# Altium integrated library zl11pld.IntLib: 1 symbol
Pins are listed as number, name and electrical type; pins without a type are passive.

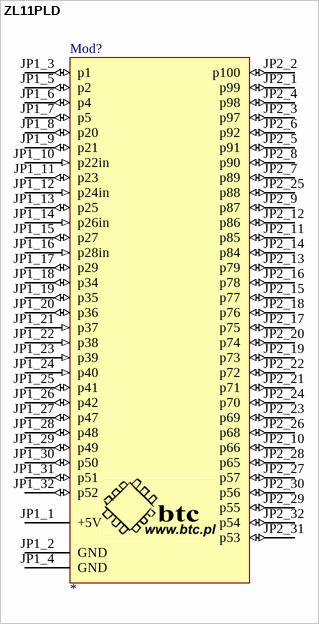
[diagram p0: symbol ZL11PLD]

## ZL11PLD
designator Mod?
Cyclone FPGA DIPmodule by www.kamami.com
footprint ZL11PLD_PCB
pins: JP1_1 +5V (power), JP1_2 GND (power), JP1_3 p1 (io), JP1_4 GND (power), JP1_5 p2 (io), JP1_6 p4 (io), JP1_7 p5 (io), JP1_8 p20 (io), JP1_9 p21 (io), JP1_10 p22in (in), JP1_11 p23 (io), JP1_12 p24in (in), JP1_13 p25 (io), JP1_14 p26in (in), JP1_15 p27 (io), JP1_16 p28in (in), JP1_17 p29 (io), JP1_18 p34 (io), JP1_19 p35 (io), JP1_20 p36 (io), JP1_21 p37 (in), JP1_22 p38 (in), JP1_23 p39 (in), JP1_24 p40 (in), JP1_25 p41 (io), JP1_26 p42 (io), JP1_27 p47 (io), JP1_28 p48 (io), JP1_29 p49 (io), JP1_30 p50 (io), JP1_31 p51 (io), JP1_32 p52 (io), JP2_1 p99 (io), JP2_2 p100 (io), JP2_3 p97 (io), JP2_4 p98 (io), JP2_5 p91 (io), JP2_6 p92 (io), JP2_7 p89 (io), JP2_8 p90 (io), JP2_9 p87 (io), JP2_10 p66 (io), JP2_11 p85 (io), JP2_12 p86 (io), JP2_13 p79 (io), JP2_14 p84 (io), JP2_15 p77 (io), JP2_16 p78 (io), JP2_17 p75 (io), JP2_18 p76 (io), JP2_19 p73 (io), JP2_20 p74 (io), JP2_21 p71 (io), JP2_22 p72 (io), JP2_23 p69 (io), JP2_24 p70 (io), JP2_25 p88 (io), JP2_26 p68 (io), JP2_27 p57 (io), JP2_28 p65 (io), JP2_29 p55 (io), JP2_30 p56 (io), JP2_31 p53 (io), JP2_32 p54 (io)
